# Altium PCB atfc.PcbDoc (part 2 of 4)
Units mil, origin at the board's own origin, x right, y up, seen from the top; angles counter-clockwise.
Board outline 6334.43 x 4147 mil, 6 copper layers (Component Side, Ground Plane (GND), GND/Signal, VCCO/Signal, VCCINT/VCCAUX, Bottom Side), stack 60.473 mil thick; 297 components, 274 nets, 1530 pads, 922 vias.
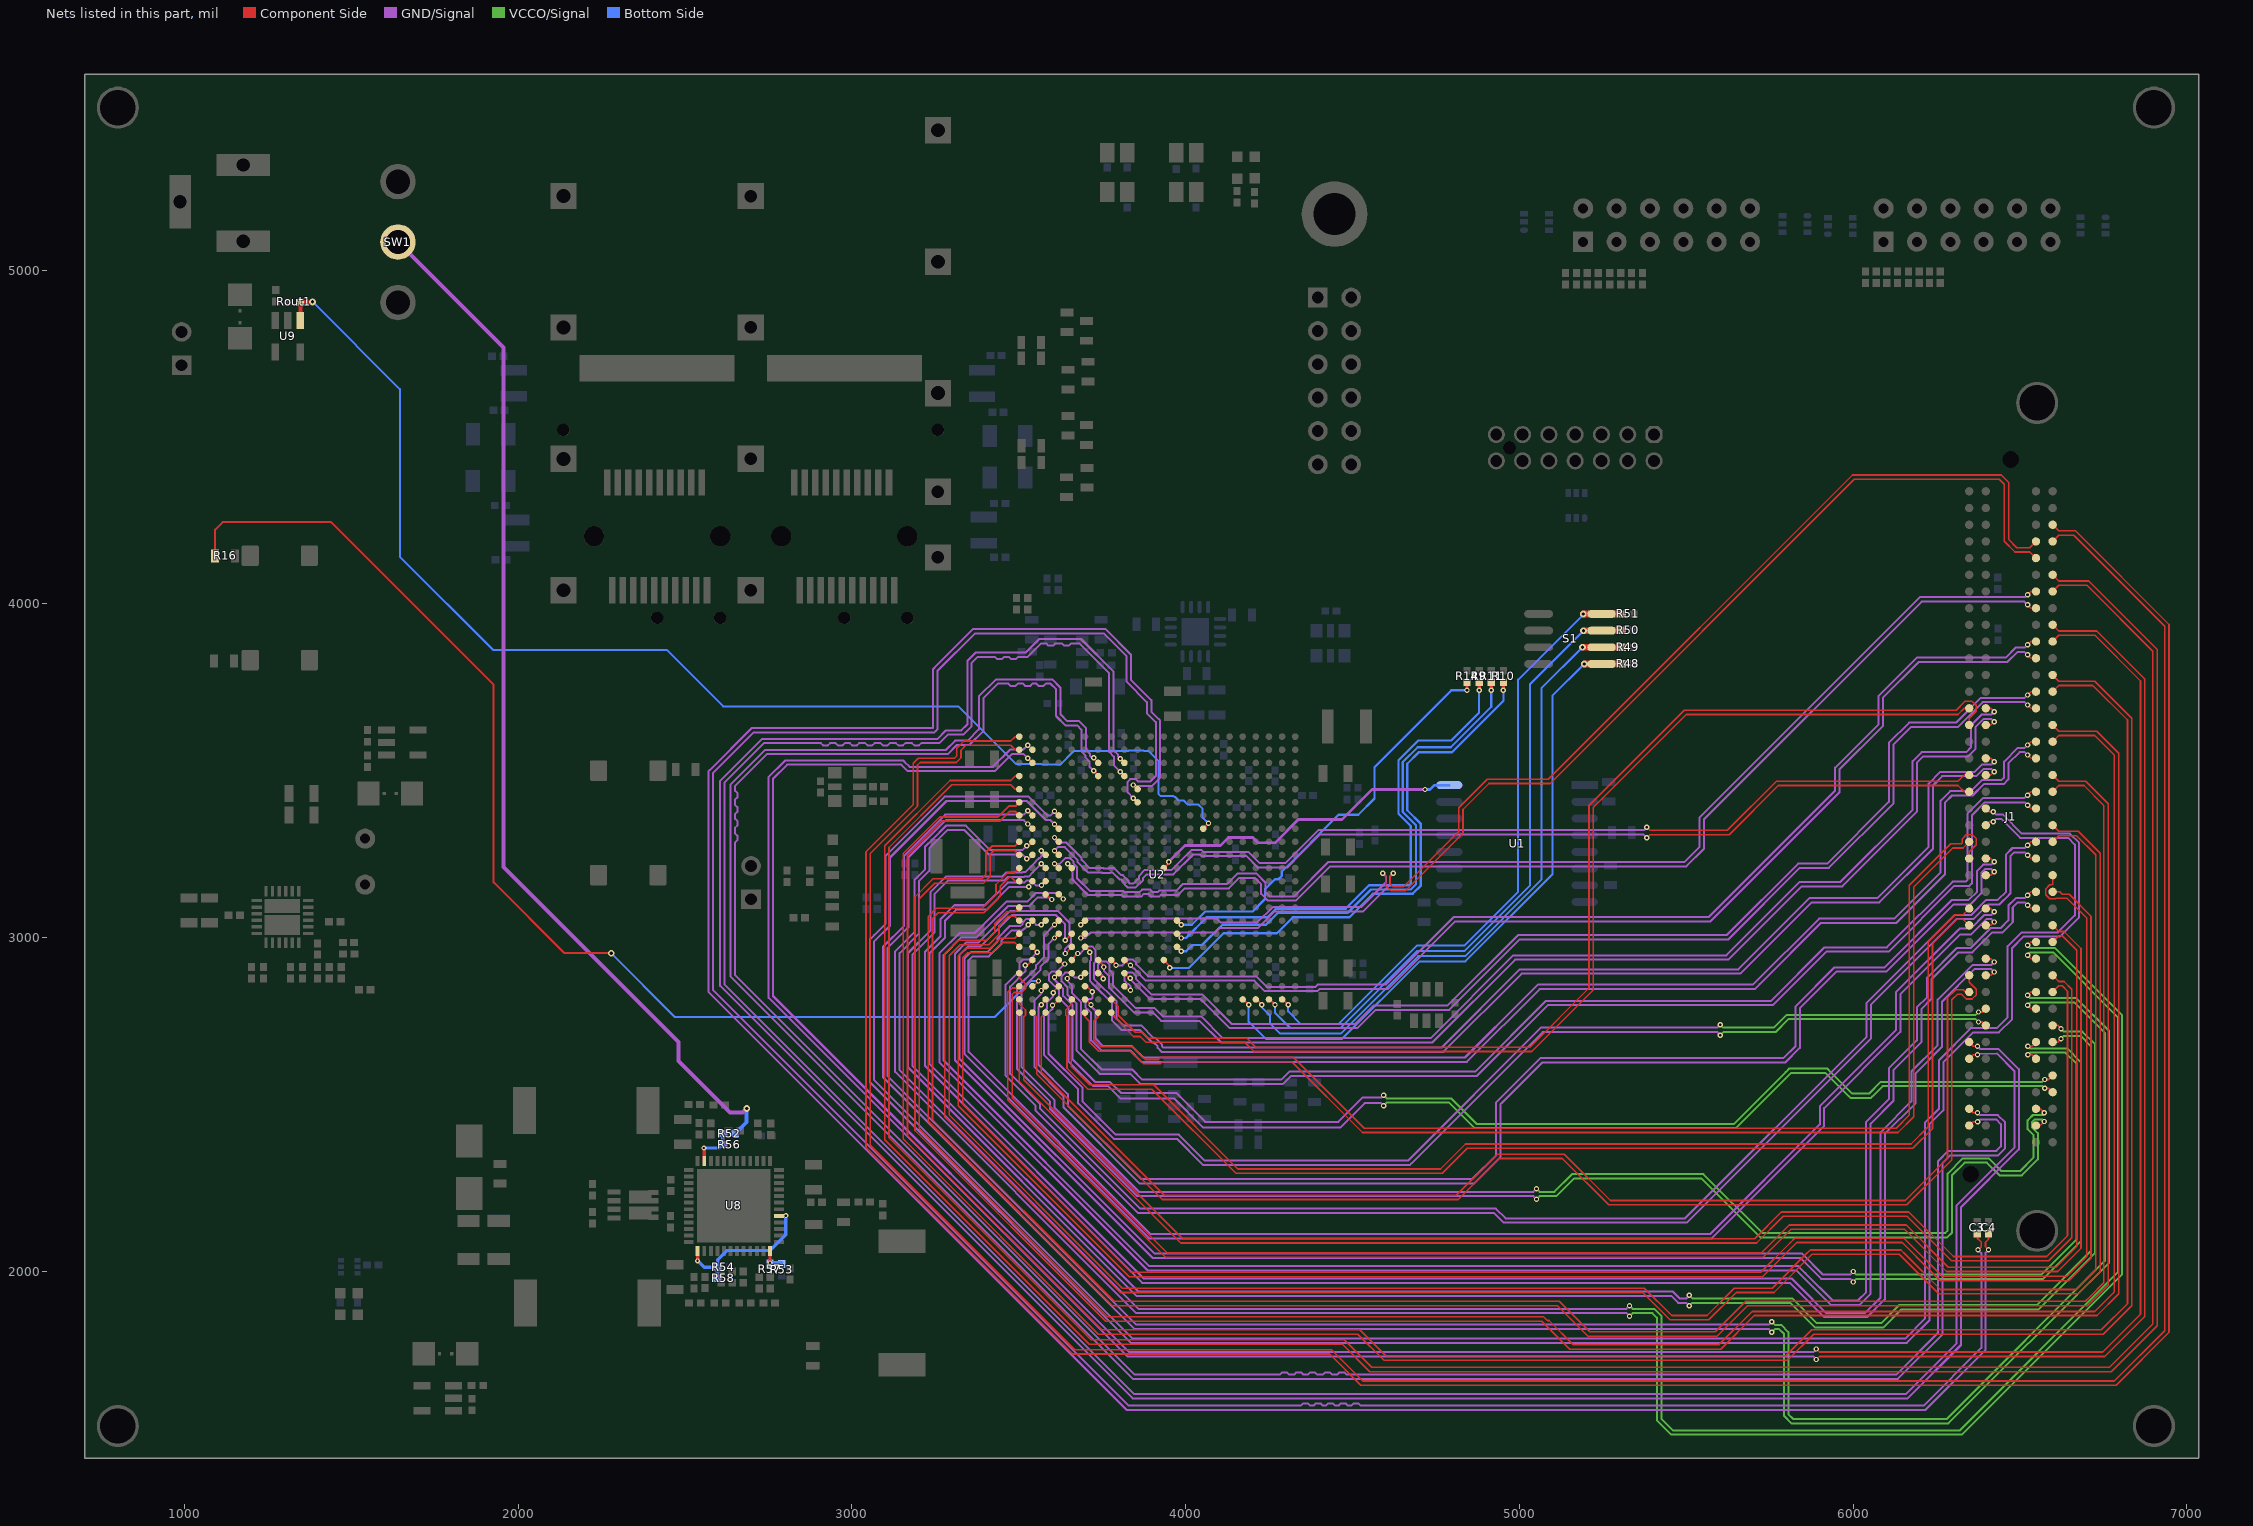
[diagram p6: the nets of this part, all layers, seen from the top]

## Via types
v1: diameter 16, hole 8, Component Side to Bottom Side, tented both sides, 374 vias
v2: diameter 20, hole 10, Component Side to Bottom Side, 243 vias
v3: diameter 16, hole 8, Component Side to Bottom Side, 222 vias
v4: diameter 15, hole 7, Component Side to Bottom Side, 58 vias
v5: diameter 25, hole 10, Component Side to Bottom Side, 20 vias
v6: diameter 19.68, hole 7.87, Component Side to Bottom Side, 4 vias
v7: diameter 20, hole 10, Component Side to Bottom Side, tented both sides, 1 vias

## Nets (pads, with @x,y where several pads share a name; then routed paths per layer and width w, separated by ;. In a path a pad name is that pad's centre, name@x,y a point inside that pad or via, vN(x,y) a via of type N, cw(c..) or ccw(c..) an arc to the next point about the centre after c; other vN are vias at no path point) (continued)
12V0_I_MON: Rout1.2 U2.H15 U9.1 | length 3847.6
  Component Side w6: U2.H15@4052.8,3326.8 v1(4068.54,3342.54)
  Component Side w12: Rout1.2@1346.84,4904.77 Rout1.2@1348.73,4904.77 ; U9.1@1348.73,4850.3 Rout1.2@1348.73,4904.77 ; v2(1384.15,4904.77) Rout1.2@1348.73,4904.77
  Bottom Side w6: v2(1384.15,4904.77) 1645.67,4643.25 1645.67,4141.33 1924.8,3862.2 2444.88,3862.2 2614.17,3692.91 3318.71,3692.91 3490.98,3520.65 3553.31,3520.65 3553.63,3520.96 3567.71,3520.96 3569.34,3519.33 3625.33,3519.33 3662.46,3556.46 3662.55,3556.46 3665.1,3559 3717.81,3559 3718.11,3558.7 3732.19,3558.7 3732.49,3559 3827.9,3559 3829.45,3560.54 3873.75,3560.54 3875.59,3558.7 3889.3,3558.7 3918,3530 3918,3431 3924,3425 3963,3425 3966,3422 3968.04,3422 3979.04,3411 3994.66,3411 4006.77,3398.89 4038.54,3398.89 4051.18,3386.25 4051.18,3359.91 v1(4068.54,3342.54)
BTN_RESETN: R16.1 U2.Y2 | length 3592
  Component Side w6: R16.1@1092.47,4144 1092.47,4222.47 1115,4245 1440,4245 1927,3758 1927,3166 2139,2954 v2@2279,2954 ; U2.Y2@3540.98,2846.98 U2.Y2@3540.98,2854.35 3543.33,2854.35 v1(3559.06,2870.08)
  Bottom Side w6: v2(2279,2953) 2470,2762 3427.35,2762 3504.18,2838.83 3504.43,2838.58 3535.93,2870.08 v1(3559.06,2870.08)
CCLK: U1.16 U2.L12 | length 979.7
  Component Side w6: U2.L12@3934.69,3208.68 3949,3223 v1(3949,3227) 3953,3227 v1@3954.37,3228.37
  GND/Signal w8: v1(3949,3227) 3998,3276 4104,3276 4128,3300 4201,3300 4217,3284 4267.31,3284 4337.31,3354 4363.04,3354 4363.37,3354.33 4468.5,3354.33 4558.17,3444 v3(4717,3444)
  Bottom Side w8: v3(4717,3444) 4732,3444 4745,3457 U1.16@4790,3457
DIP1: R48.1 S1.1 U2.AA18 | length 1992
  Component Side w6: U2.AA18@4170.91,2814.98 4173.2,2814.98 v1(4188.98,2799.21)
  Component Side w20: v2(5194,3820) S1.1@5246.49,3820 ; S1.1@5247.49,3821 R48.1@5306.27,3821
  Bottom Side w6: v1(4188.98,2799.21) 4188.98,2748.03 4240.16,2696.85 4468.5,2696.85 4700.79,2929.13 4838.31,2929.13 5098.43,3189.25 5098.43,3724.43 v2(5194,3820)
DIP2: R49.1 S1.2 U2.AA19 | length 1973
  Component Side w6: U2.AA19@4210.28,2814.98 4212.57,2814.98 v1(4228.35,2799.21)
  Component Side w20: v2(5189,3870) S1.2@5246.49,3870 R49.1@5307.27,3870
  Bottom Side w6: v1(4228.35,2799.21) 4228.35,2791.34 4251.97,2767.72 4251.97,2744.09 4283.46,2712.6 4464.57,2712.6 4696.85,2944.88 4837.09,2944.88 5066,3173.79 5066,3747 v2(5189,3870)
DIP3: R50.1 S1.3 U2.AA20 | length 1956.1
  Component Side w6: U2.AA20@4249.65,2814.98 4251.94,2814.98 v1(4267.72,2799.21)
  Component Side w20: v2(5192,3920) S1.3@5246.49,3920 ; S1.3@5248.49,3920 5247.49,3921 R50.1@5307.27,3921 R50.1@5309.27,3921
  Bottom Side w6: v1(4267.72,2799.21) 4267.72,2775.59 4314.15,2729.16 4462.66,2729.16 4694.14,2960.63 4835.87,2960.63 5032,3156.76 5032,3760 v2(5192,3920)
DIP4: R51.1 S1.4 U2.AA21 | length 1943.7
  Component Side w6: U2.AA21@4289.02,2814.98 4291.31,2814.98 v1(4307.09,2799.21)
  Component Side w20: v2(5191,3970) S1.4@5246.49,3970 R51.1@5307.27,3970 R51.1@5308.27,3970
  Bottom Side w6: v1(4307.09,2799.21) 4307.09,2779.53 4345.46,2741.16 4457.69,2741.16 4692.91,2976.38 4834.65,2976.38 4996.06,3137.8 4996.06,3773.19 5191,3968.13 v2(5191,3970)
EN: R52.2 SW1.2 | length 3164.7
  GND/Signal w12: SW1.2@1640,5084 1956,4768 1956,3212 2480.32,2687.68 2480.32,2630.68 2635,2476 2672.85,2476 v2(2685.03,2488.18)
  Bottom Side w12: R52.2@2650.48,2413 2685.03,2447.55 v2(2685.03,2488.18)
ES1: R52.1 R56.2 U8.23 | length 129
  Component Side w10: U8.23@2557.73,2331.43 v4@2557.73,2368.95
  Bottom Side w10: v4(2556.68,2370) 2603,2370 2613,2380 R52.1@2613,2411
ES2: R53.1 R57.2 U8.48 | length 70.4
  Component Side w10: v4@2754.58,2025.79 U8.48@2754.58,2061.14
  Bottom Side w10: v4(2754.69,2025.68) R53.1@2789.68,2025.68
ES3: R54.1 R58.2 U8.5 U8.37 | length 457.7
  Component Side w10: v4@2538.05,2032.36 U8.37@2538.05,2061.14 ; U8.5@2781.46,2166.76 2781.7,2167 v4(2802,2167)
  Bottom Side w10: v4@2538.68,2032 2557.68,2013 R54.1@2595,2013 ; R58.2@2596,1982 R54.1@2596,2012 ; R54.1@2597.95,2013 2597.95,2034.95 2625.61,2062.61 2754.61,2062.61 2802,2110 v4(2802,2167)
  other v4: 2537.68,2032
FMC_CLK0_M2C_N: J1.H5 U2.W4 | length 3490.6
  Component Side w5: v3(6573.44,2575.2) 6585.44,2575.2 J1.H5@6597.44,2587.2
  Component Side w6: v1(3607.04,2881.04) U2.W4@3619.72,2893.72
  GND/Signal w6: v1(3607.04,2881.04) 3607.04,2873.39 3633,2847.43 3633,2825.4 3661.3,2797.1 3661.3,2635.09 3728.38,2568 3773.22,2568 3806.22,2535 3971.99,2535 4058.53,2448.46 4457.46,2448.46 4529.47,2520.47 4585.48,2520.47 v3(4593,2527.99)
  VCCO/Signal w6: v3(4593,2527.99) 4602.25,2518.74 4794.92,2518.74 4871.4,2442.26 5643.05,2442.26 5797.79,2597 5808.79,2608 5922.2,2608 5933.2,2597 5997.38,2532.81 6047.37,2532.81 6082.68,2568.12 6566.35,2568.12 v3(6573.44,2575.2)
FMC_CLK0_M2C_P: J1.H4 U2.V4 | length 3589.2
  Component Side w5: v3(6573.44,2549.2) 6585.44,2549.2 J1.H4@6597.44,2537.2
  Component Side w6: U2.V4@3619.72,2933.09 3631.56,2921.26 v1(3637.8,2921.26)
  GND/Signal w6: v1(3637.8,2921.26) 3615.57,2899.04 3599.58,2899.04 3590,2889.46 3590,2872.04 3620,2842.04 3620,2820.01 3648.3,2791.71 3648.3,2629.7 3723,2555 3767.83,2555 3804.29,2518.54 3965.17,2518.54 4051.72,2432 4464.27,2432 4536.29,2504.02 4585.48,2504.02 v3(4593,2496.5)
  VCCO/Signal w6: v3(4593,2496.5) 4602.25,2505.74 4789.53,2505.74 4862.2,2433.07 4866.01,2429.26 5648.44,2429.26 5652.24,2433.07 5814.17,2595 5916.81,2595 5988.19,2523.62 5992,2519.81 6052.76,2519.81 6056.57,2523.62 6088.06,2555.12 6567.53,2555.12 v3(6573.44,2549.2)
FMC_CLK1_M2C_N: J1.G3 U2.T4 | length 4181.3
  Component Side w5: J1.G3@6547.44,2487.2 6560.44,2487.2 v3(6572.44,2475.2)
  Component Side w6: v1(3607.04,2999.15) U2.T4@3619.72,3011.83
  GND/Signal w6: v1(3607.04,2999.15) 3589.3,2981.41 3589.3,2936.84 3564.95,2912.49 3564.95,2902.86 3507.7,2845.62 3507.7,2613.3 3606.82,2514.18 3606.82,2492.18 3860.22,2238.78 5041.93,2238.78 v3(5051.18,2248.03)
  VCCO/Signal w6: v3(5051.18,2248.03) 5060.43,2238.78 5104.93,2238.78 5157.48,2291.34 5551.18,2291.34 5727.16,2115.36 6276.36,2115.36 6283,2122 6283,2293.38 6328.62,2339 6405.77,2339 6443.77,2301 6500,2301 6540,2341 6540,2409 6526,2423 6522.19,2426.81 6522.19,2452.28 6526,2456.09 6538.62,2468.7 6565.94,2468.7 v3(6572.44,2475.2)
FMC_CLK1_M2C_P: J1.G2 U2.R4 | length 4247.6
  Component Side w5: J1.G2@6547.44,2437.2 6560.44,2437.2 v3(6572.44,2449.2)
  Component Side w6: v1(3607.04,3038.52) U2.R4@3619.72,3051.2
  GND/Signal w6: v1(3607.04,3038.52) 3576.3,3007.78 3576.3,2942.22 3551.95,2917.87 3551.95,2908.25 3494.7,2851 3494.7,2607.91 3593.82,2508.8 3593.82,2486.8 3854.83,2225.78 5041.93,2225.78 v3(5051.18,2216.54)
  VCCO/Signal w6: v3(5051.18,2216.54) 5060.43,2225.78 5110.31,2225.78 5162.87,2278.34 5545.8,2278.34 5698.15,2125.98 5721.77,2102.36 6281.75,2102.36 6296,2116.62 6296,2288 6334,2326 6400.38,2326 6438.38,2288 6505.38,2288 6553,2335.62 6553,2414.38 6535.19,2432.19 6535.19,2446.9 6544,2455.7 6565.94,2455.7 v3(6572.44,2449.2)
FMC_LA00_CC_N: J1.G7 U2.U5 | length 5304.4
  Component Side w5: v3(6523.44,2675.2) 6535.44,2675.2 J1.G7@6547.44,2687.2
  Component Side w6: v1(3639.09,2952.46) U2.U5@3659.09,2972.46
  GND/Signal w6: v1(3639.09,2952.46) 3639.09,2966.38 3657.09,2984.38 3657.09,2999.29 3652.09,3004.29 3652.09,3045.29 3626.19,3071.19 3616.86,3080.52 3474.14,3080.52 3379.62,2986 3342.62,2986 3309,2952.38 3309,2632.62 3900.62,2041 5840.82,2041 5904.06,1977.75 5990.75,1977.75 v3(6000,1968.5)
  VCCO/Signal w6: v3(6000,1968.5) 6009.25,1977.75 6569.14,1977.75 6682.29,2090.91 6682.29,2627.43 6641.02,2668.7 6529.94,2668.7 v3(6523.44,2675.2)
FMC_LA00_CC_P: J1.G6 U2.T5 | length 5147.8
  Component Side w5: v3(6523.44,2649.2) 6535.44,2649.2 J1.G6@6547.44,2637.2
  Component Side w6: v1(3639.09,2991.83) U2.T5@3659.09,3011.83
  GND/Signal w6: v1(3639.09,2991.83) 3639.09,3039.91 3611.48,3067.52 3479.52,3067.52 3385,2973 3348,2973 3322,2947 3322,2638 3906,2054 5846.2,2054 5909.45,1990.75 5990.75,1990.75 v3(6000,2000)
  VCCO/Signal w6: v3(6000,2000) 6009.25,1990.75 6563.75,1990.75 6669.29,2096.29 6669.29,2622.05 6635.63,2655.7 6529.94,2655.7 v3(6523.44,2649.2)
FMC_LA01_CC_N: J1.D9 U2.AA4 | length 3324.7
  Component Side w5: v1(3601,2798) 3602.74,2798 U2.AA4@3619.72,2814.98 ; v3(6375.44,2777.2) 6387.44,2777.2
  GND/Signal w6: v1@3602.02,2798 v1(3601,2798) 3601,2787 3589,2775 3589,2653 3691.18,2550.82 3691.18,2508.82 3790,2410 3979.38,2410 4057.19,2332.19 4666.19,2332.19 5064.25,2730.25 5592.75,2730.25 v3(5602,2739.5)
  VCCO/Signal w6: v3(5602,2739.5) 5611.25,2730.25 5761.86,2730.25 5800.32,2768.7 6366.94,2768.7 v3(6375.44,2777.2)
FMC_LA01_CC_P: J1.D8 U2.Y4 | length 3389.2
  Component Side w5: v3(6375.44,2747.2) 6387.44,2747.2
  Component Side w6: v1(3603,2835) 3603,2837.63 U2.Y4@3619.72,2854.35
  GND/Signal w6: v1(3603,2835) 3603,2824.04 3584,2805.04 3584,2788.38 3575.81,2780.19 3576,2780 3576,2648 3575.81,2647.81 3678.18,2545.44 3678.18,2503.44 3784.62,2397 3974,2397 4048,2323 4051.81,2319.19 4671.58,2319.19 4675.38,2323 5069.63,2717.25 5592.75,2717.25 v3(5602,2708)
  VCCO/Signal w6: v3(5602,2708) 5611.25,2717.25 5767.25,2717.25 5805.7,2755.7 6366.94,2755.7 v3(6375.44,2747.2)
FMC_LA02_N: J1.H8 U2.K3 | length 5721.1
  Component Side w5: J1.H8@6597.44,2737.2 6612.44,2737.2 v3(6622.44,2727.2)
  Component Side w6: v1(3567.67,3260.74) U2.K3@3580.35,3248.06
  GND/Signal w6: v1(3567.67,3260.74) 3567.67,3243.67 3562.37,3238.37 3560.63,3238.37 3550.67,3228.41 3550.67,3227.46 3519.34,3196.13 3512.13,3196.13 3511,3195 3461.26,3195 3450.26,3184 3282.43,3184 3235.03,3136.61 3235.03,3021.13 3168.1,2954.2 3168.1,2611.51 3852.62,1927 5454.44,1927 5475.44,1906 5500,1906 v3(5509,1897)
  VCCO/Signal w6: v3(5509,1897) 5518.25,1906.25 5811.75,1906.25 5886,1832 6089.38,1832 6143.19,1885.81 6554.81,1885.81 6701,2032 6725,2056 6725,2680.38 6686.68,2718.7 6630.94,2718.7 v3(6622.44,2727.2)
FMC_LA02_P: J1.H7 U2.L3 | length 5613.8
  Component Side w5: J1.H7@6597.44,2687.2 6612.44,2687.2 v3(6622.44,2697.2)
  Component Side w6: v1(3567.67,3221.37) U2.L3@3580.35,3208.68
  GND/Signal w6: v1(3567.67,3221.37) 3552.28,3205.98 3552.01,3205.98 3542.06,3196.02 3542.06,3195.76 3529.43,3183.13 3517.51,3183.13 3516.38,3182 3466.64,3182 3455.64,3171 3287.81,3171 3248.03,3131.22 3248.03,3015.75 3181.1,2948.82 3181.1,2616.9 3858,1940 5459.83,1940 5480.83,1919 5499.5,1919 v3(5509,1928.5)
  VCCO/Signal w6: v3(5509,1928.5) 5518.25,1919.25 5817.14,1919.25 5891.38,1845 6084,1845 6134,1895 6137.81,1898.81 6549.42,1898.81 6712,2061.38 6712,2675 6681.3,2705.7 6630.94,2705.7 v3(6622.44,2697.2)
FMC_LA03_N: J1.G10 U2.G2 | length 6602.3
  Component Side w5: v3(6522.44,2827.2) 6532.44,2837.2 J1.G10@6547.44,2837.2
  Component Side w6: v1(3526.98,3380.17) U2.G2@3540.98,3366.17
  GND/Signal w6: v1(3526.98,3380.17) 3515.53,3368.71 3279.46,3368.71 3156.29,3245.54 3156.29,3036.29 3093.3,2973.3 3093.3,2581.32 3846.62,1828 3885,1828 3886,1827 5747,1827 v3(5756,1818)
  VCCO/Signal w6: v3(5756,1818) 5765.25,1827.25 5778.38,1827.25 5793,1812.63 5793,1567 5815,1545 6285.38,1545 6767,2026.62 6767,2720.38 6668.68,2818.7 6530.94,2818.7 v3(6522.44,2827.2)
FMC_LA03_P: J1.G9 U2.H2 | length 6514.1
  Component Side w5: v3(6522.44,2797.2) 6532.44,2787.2 J1.G9@6547.44,2787.2
  Component Side w6: v1(3526.98,3340.8) U2.H2@3540.98,3326.8
  GND/Signal w6: v1(3526.98,3340.8) 3515.53,3352.25 3281.39,3352.25 3169.29,3240.16 3169.29,3030.91 3106.3,2967.91 3106.3,2586.7 3852,1841 5747.5,1841 v3(5756,1849.5)
  VCCO/Signal w6: v3(5756,1849.5) 5765.25,1840.25 5783.77,1840.25 5806,1818.02 5806,1572.38 5820.38,1558 6280,1558 6754,2032 6754,2715 6663.3,2805.7 6530.94,2805.7 v3(6522.44,2797.2)
FMC_LA04_N: J1.H11 U2.AB1 | length 4496.4
  Component Side w5: U2.AB1@3501.61,2775.61 3501.61,2569.25 3985.44,2085.43 5710.11,2085.43 5790.04,2165.35 6161.42,2165.35 6291.34,2035.43 6295.15,2031.63 6585.44,2031.63 6655,2101.18 6655,2845.07 6631.37,2868.7 6615.94,2868.7 J1.H11@6597.44,2887.2
FMC_LA04_P: J1.H10 U2.AA1 | length 4480.9
  Component Side w5: U2.AA1@3501.61,2814.98 3501.61,2801.55 3519.96,2783.21 3519.96,2768.02 3514.61,2762.67 3514.61,2574.64 3990.83,2098.43 5704.72,2098.43 5784.65,2178.35 6166.8,2178.35 6300.53,2044.63 6580.06,2044.63 6642,2106.57 6642,2839.69 6625.98,2855.7 6615.94,2855.7 J1.H10@6597.44,2837.2
FMC_LA05_N: J1.D12 U2.M2 | length 5151.4
  Component Side w5: v1(3530,3153) 3530,3158.33 U2.M2@3540.98,3169.31 ; J1.D12@6397.44,2937.2 6412.44,2937.2 v3(6422.44,2927.2)
  GND/Signal w6: v1@3530,3152 3472,3152 3404.17,3084.17 3312.56,3084.17 3279,3050.62 3279,2999.62 3232,2952.62 3232,2622 3875,1979 5815.38,1979 5839.38,1955 5918.38,1876 6036,1876 6082,1922 6082,2417.38 6174,2509.38 6174,2599 6253,2678 6253,2814.09 6357.62,2918.7 6413.94,2918.7 v3(6422.44,2927.2) ; v1(3530,3153) v1@3530,3156
FMC_LA05_P: J1.D11 U2.M3 | length 5234.4
  Component Side w5: J1.D11@6397.44,2887.2 6412.44,2887.2 v3(6422.44,2897.2)
  Component Side w6: v1(3568,3157) U2.M3@3580.35,3169.31
  GND/Signal w6: v1(3568,3157) 3551,3157 3536.87,3171.13 3522.49,3171.13 3516.36,3165 3466.62,3165 3398.79,3097.17 3307.17,3097.17 3266,3056 3266,3005 3219,2958 3219,2616.62 3869.62,1966 5810,1966 5913,1863 6041.38,1863 6095,1916.62 6095,2412 6187,2504 6187,2593.62 6266,2672.62 6266,2808.7 6363,2905.7 6413.94,2905.7 v3(6422.44,2897.2)
FMC_LA06_N: J1.C11 U2.AB2 | length 3889.2
  Component Side w5: U2.AB2@3540.98,2775.61 3554.17,2762.43 3554.17,2591.5 3930.32,2215.35 4816.41,2215.35 4939.64,2338.58 5128.47,2338.58 5267.46,2199.6 6160.9,2199.6 6295.28,2333.98 6295.28,2813.7 6312.29,2830.71 6324.24,2830.71 6338.74,2816.2 6356.14,2816.2 6368.44,2828.51 6368.44,2845.9 6347.44,2866.9 J1.C11@6347.44,2887.2
FMC_LA06_P: J1.C10 U2.AB3 | length 3775.5
  Component Side w5: U2.AB3@3580.35,2775.61 3567.17,2762.43 3567.17,2596.88 3935.71,2228.35 4811.02,2228.35 4934.26,2351.58 5133.86,2351.58 5272.84,2212.6 6155.51,2212.6 6282.28,2339.36 6282.28,2819.08 6306.9,2843.71 6329.62,2843.71 6341.78,2831.55 J1.C10@6347.44,2837.2
FMC_LA07_N: J1.H14 U2.Y1 | length 4901.9
  Component Side w5: U2.Y1@3501.61,2854.35 3496.27,2849.01 3480.23,2849.01 3467.32,2836.09 3467.32,2514.3 3939.5,2042.12 5729.79,2042.12 5813.66,2125.98 6153.54,2125.98 6279.53,2000 6612.87,2000 6682.29,2069.42 6682.29,2967.78 6631.37,3018.7 6615.94,3018.7 J1.H14@6597.44,3037.2
FMC_LA07_P: J1.H13 U2.W1 | length 4890.9
  Component Side w5: U2.W1@3501.61,2893.72 3501.61,2880.29 3519.96,2861.95 3519.96,2846.76 3509.21,2836.01 3485.62,2836.01 3480.32,2830.71 3480.32,2519.68 3944.88,2055.12 5724.41,2055.12 5782.28,2112.98 5808.28,2138.98 6158.93,2138.98 6284.91,2013 6607.49,2013 6669.29,2074.8 6669.29,2962.4 6625.98,3005.7 6615.94,3005.7 J1.H13@6597.44,2987.2
FMC_LA08_N: J1.G13 U2.J2 | length 6789.6
  Component Side w5: v3(6522.44,2977.2) 6532.44,2987.2 J1.G13@6547.44,2987.2
  Component Side w6: v1(3523.62,3275.59) 3529.15,3275.59 U2.J2@3540.98,3287.43
  GND/Signal w6: v1(3523.62,3275.59) 3510.43,3262.4 3414.76,3262.4 3341.33,3335.83 3282.02,3335.83 3240.16,3293.98 3219.28,3273.1 3219.28,3205.32 3187.79,3173.83 3187.79,3017.2 3148.29,2977.7 3129.92,2959.33 3129.92,2597.69 3852.62,1875 5321,1875 v3(5330,1866)
  VCCO/Signal w6: v3(5330,1866) 5339.25,1875.25 5398.37,1875.25 5412,1861.62 5412,1553.62 5454.62,1511 6325.38,1511 6786.19,1971.81 6806,1991.62 6806,2767.38 6604.68,2968.7 6530.94,2968.7 v3(6522.44,2977.2)
FMC_LA08_P: J1.G12 U2.K2 | length 6703.7
  Component Side w5: v3(6522.44,2947.2) 6532.44,2937.2 J1.G12@6547.44,2937.2
  Component Side w6: v1(3523.61,3236.21) 3529.14,3236.21 U2.K2@3540.98,3248.06
  GND/Signal w6: v1(3523.61,3236.21) 3510.43,3249.4 3409.38,3249.4 3335.95,3322.83 3287.4,3322.83 3232.28,3267.72 3232.28,3199.94 3200.79,3168.44 3200.79,3011.81 3142.92,2953.95 3142.92,2603.08 3858,1888 5320.5,1888 v3(5330,1897.5)
  VCCO/Signal w6: v3(5330,1897.5) 5339.25,1888.25 5403.75,1888.25 5425,1867 5425,1559 5460,1524 6320,1524 6793,1997 6793,2762 6599.3,2955.7 6530.94,2955.7 v3(6522.44,2947.2)
FMC_LA09_N: J1.D15 U2.R2 | length 4345.2
  Component Side w5: J1.D15@6397.44,3087.2 6412.44,3087.2 v3(6422.44,3077.2)
  Component Side w6: v1(3528.3,3038.52) U2.R2@3540.98,3051.2
  GND/Signal w6: v1(3528.3,3038.52) 3515.84,3026.06 3515.13,3026.06 3511.18,3022.11 3479.11,3022.11 3449,2992 3449,2982.62 3410.38,2944 3362,2944 3350,2932 3350,2658 3896,2112 5571,2112 5900,2441 5900,2495 6128,2723 6128,2836 6315,3023 6319,3027 6351.62,3027 6393.32,3068.7 6413.94,3068.7 v3(6422.44,3077.2)
FMC_LA09_P: J1.D14 U2.R3 | length 4439.3
  Component Side w5: J1.D14@6397.44,3037.2 6412.44,3037.2 v3(6422.44,3047.2)
  Component Side w6: v1(3567.67,3038.52) U2.R3@3580.35,3051.2
  GND/Signal w6: v1(3567.67,3038.52) 3552.34,3038.52 3535.34,3055.52 3521.26,3055.52 3511.3,3045.56 3511.3,3040.61 3505.8,3035.11 3473.73,3035.11 3436,2997.38 3436,2988 3405,2957 3356.62,2957 3340.81,2941.19 3337,2937.38 3337,2652.62 3890.62,2099 5576.38,2099 5909.19,2431.81 5913,2435.62 5913,2489.62 6141,2717.62 6141,2830.62 6320.58,3010.19 6353.19,3010.19 6398.7,3055.7 6413.94,3055.7 v3(6422.44,3047.2)
FMC_LA10_N: J1.C15 U2.AB5 | length 3627.2
  Component Side w5: U2.AB5@3659.09,2775.61 3659.09,2763.27 3657.48,2761.66 3657.48,2614.17 3712.6,2559.06 3904.21,2559.06 4156.18,2307.09 4763.78,2307.09 4838.58,2381.89 6173.23,2381.89 6224.41,2433.07 6224.41,2987.48 6305.64,3068.7 6328.94,3068.7 J1.C15@6347.44,3087.2
FMC_LA10_P: J1.C14 U2.AA5 | length 3696.6
  Component Side w5: U2.AA5@3659.09,2814.98 3659.09,2801.55 3640.75,2783.21 3640.75,2768.02 3644.48,2764.29 3644.48,2608.79 3707.21,2546.06 3791.34,2546.06 3898.82,2546.06 4150.8,2294.09 4769.16,2294.09 4843.97,2368.89 6178.61,2368.89 6237.41,2427.69 6237.41,2982.09 6311.02,3055.7 6328.94,3055.7 J1.C14@6347.44,3037.2
FMC_LA11_N: J1.H17 U2.U1 | length 5562.1
  Component Side w5: U2.U1@3501.61,2972.46 3488.43,2985.65 3450.17,2985.65 3419.65,2955.13 3347.53,2955.13 3331.9,2939.5 3331.9,2501.45 3836.09,1997.25 5722.96,1997.25 5812.32,2086.61 5825.32,2099.61 6152.35,2099.61 6165.35,2086.61 6266.53,1985.44 6640.28,1985.44 6699.6,2044.75 6699.6,3059.06 6640.54,3118.11 6608.04,3118.11 6606.14,3116.2 6588.74,3116.2 6576.44,3128.51 6576.44,3145.9 6588.74,3158.2 6595.21,3158.2 6597.44,3160.43 J1.H17@6597.44,3187.2
FMC_LA11_P: J1.H16 U2.T1 | length 5552.8
  Component Side w5: U2.T1@3501.61,3011.83 3488.43,2998.65 3444.79,2998.65 3414.26,2968.13 3342.14,2968.13 3318.9,2944.88 3318.9,2496.06 3830.71,1984.25 5728.35,1984.25 5830.71,2086.61 6146.97,2086.61 6230.97,2002.62 6261.14,1972.44 6645.67,1972.44 6712.6,2039.37 6712.6,3064.44 6647.12,3129.92 6625.98,3129.92 6618.7,3137.2 J1.H16@6597.44,3137.2
FMC_LA12_N: J1.G16 U2.N3 | length 5300.2
  Component Side w5: v3(6522.44,3127.2) 6532.44,3137.2 J1.G16@6547.44,3137.2
  Component Side w6: U2.N3@3580.35,3129.94 3597.28,3113.02 3598.43,3111.87 3599.57,3113.02 v1@3600.72,3114.17 ; v1(3598.42,3114.17) v1@3600.72,3114.17 ; v1@3602.36,3115.81 v1@3600.72,3114.17
  GND/Signal w6: v1@3602.36,3115 3601.53,3114.17 v1(3598.42,3114.17) 3591.59,3121 3557,3121 3531,3095 3468,3095 3404.02,3031.02 3404.02,3030.88 3386.44,3013.31 3386.31,3013.31 3374,3001 3328,3001 3275,2948 3275,2632 3891,2016 5835.38,2016 5856.38,1995 5938.38,1913 6014,1913 6039,1938 6039,2448 6107,2516 6107,2608.38 6191,2692.38 6191,2791.38 6221.62,2822 6221.62,2880.62 6310,2969 6351.62,2969 6411.62,3029 6442,3029 6465,3052 6465,3096.38 6483.51,3114.9 6487.32,3118.7 6513.94,3118.7 v3(6522.44,3127.2)
FMC_LA12_P: J1.G15 U2.N4 | length 5365.4
  Component Side w5: v3(6522.44,3097.2) 6532.44,3087.2 J1.G15@6547.44,3087.2
  Component Side w6: U2.N4@3619.72,3129.94 v1(3633.72,3115.94)
  GND/Signal w6: v1(3633.72,3115.94) 3615.67,3134 3551.62,3134 3525.62,3108 3462.62,3108 3391.02,3036.4 3391.02,3036.27 3381.06,3026.31 3380.92,3026.31 3368.62,3014 3322.62,3014 3262,2953.38 3262,2626.62 3885.62,2003 5830,2003 5933,1900 6019.38,1900 6048.19,1928.81 6052,1932.62 6052,2442.62 6120,2510.62 6120,2603 6204,2687 6204,2786 6234.62,2816.62 6234.62,2875.23 6315.38,2956 6357,2956 6417,3016 6447.38,3016 6478,3046.62 6478,3091 6492.7,3105.7 6513.94,3105.7 v3(6522.44,3097.2)
FMC_LA13_N: J1.D18 U2.AA3 | length 3850.9
  Component Side w5: J1.D18@6397.44,3237.2 6412.44,3237.2 v3(6422.44,3227.2)
  Component Side w6: v1(3566.92,2799.21) 3566.92,2801.55 U2.AA3@3580.35,2814.98
  GND/Signal w6: v1(3566.92,2799.21) 3559.52,2791.8 3559.52,2618.59 3647,2531.11 3647,2497 3867,2277 4859,2277 4930.13,2348.13 4930.13,2506.33 4933.9,2510.1 5062.79,2639 5791,2639 5827.5,2675.5 5827.5,2794.5 5944,2911 6094,2911 6296,3113 6346,3113 6371,3138 6371,3200.09 6389.62,3218.7 6413.94,3218.7 v3(6422.44,3227.2)
FMC_LA13_P: J1.D17 U2.Y3 | length 3917.1
  Component Side w5: J1.D17@6397.44,3187.2 6412.44,3187.2 v3(6422.44,3197.2)
  Component Side w6: v1(3567.67,2841.67) U2.Y3@3580.35,2854.35
  GND/Signal w6: v1(3567.67,2841.67) 3567.67,2832.21 3546.52,2811.06 3546.52,2613.21 3634,2525.73 3634,2491.62 3861.62,2264 4864.38,2264 4870.38,2270 ; 4870.3,2270.09 4943,2342.79 4943,2500.82 4946.9,2504.72 5068.18,2626 5796.38,2626 5840.5,2670.12 5840.5,2789.12 5949.38,2898 6099.38,2898 6301.38,3100 6351.38,3100 6384,3132.62 6384,3194.7 6395,3205.7 6413.94,3205.7 v3(6422.44,3197.2)
FMC_LA14_N: J1.C19 U2.AB6 | length 3610.9
  Component Side w5: U2.AB6@3698.46,2775.61 3698.46,2763.27 3711.65,2750.09 3711.65,2688.48 3739.9,2660.23 3835.83,2660.23 3870.08,2625.98 3873.89,2622.18 3924.03,2622.18 3927.83,2625.98 3930.45,2628.6 4317.45,2628.6 4529.92,2416.13 6134.12,2416.13 6181.1,2463.12 6181.1,3152.04 6297.76,3268.7 6328.94,3268.7 J1.C19@6347.44,3287.2
FMC_LA14_P: J1.C18 U2.AB7 | length 3693.4
  Component Side w5: U2.AB7@3737.83,2775.61 3737.83,2763.27 3724.65,2750.09 3724.65,2693.86 3745.28,2673.23 3841.22,2673.23 3879.27,2635.18 3918.64,2635.18 3921.26,2637.8 3925.07,2641.6 4322.83,2641.6 4535.3,2429.13 6128.73,2429.13 6168.1,2468.5 6168.1,3157.43 6292.38,3281.7 6323.56,3281.7 6326.44,3284.59 6326.44,3295.9 6338.74,3308.2 6357.15,3308.2 6368.44,3296.91 6368.44,3278.51 6347.44,3257.51 J1.C18@6347.44,3237.2
FMC_LA15_N: J1.H20 U2.P1 | length 6086.7
  Component Side w5: U2.P1@3501.61,3090.57 3488.43,3077.39 3463.22,3077.39 3427.95,3042.12 3427.95,3015.75 3404.32,2992.13 3318.9,2992.13 3278.34,2951.57 3278.34,2463.12 3804.45,1937.01 5369,1937.01 5451.01,1855 5567.38,1855 5649.38,1937.01 5762.48,1937.01 5876.65,2051.18 6137.8,2051.18 6255.91,1933.07 6673.23,1933.07 6739.78,1999.62 6739.78,3253.42 6674.49,3318.7 6615.94,3318.7 J1.H20@6597.44,3337.2
FMC_LA15_P: J1.H19 U2.R1 | length 6000.5
  Component Side w5: U2.R1@3501.61,3051.2 3488.43,3064.39 3468.6,3064.39 3440.95,3036.73 3440.95,3010.36 3409.71,2979.13 3324.28,2979.13 3291.34,2946.18 3291.34,2468.5 3809.83,1950.01 5374.38,1950.01 5456.39,1868 5561.99,1868 5644,1950.01 5757.09,1950.01 5858.27,2051.18 5871.27,2064.18 6143.18,2064.18 6156.18,2051.18 6261.29,1946.07 6667.84,1946.07 6726.78,2005.01 6726.78,3248.03 6669.11,3305.7 6615.94,3305.7 J1.H19@6597.44,3287.2
FMC_LA16_N: J1.G19 U2.V2 | length 4230.2
  Component Side w5: v3(6522.44,3277.2) 6532.44,3287.2 J1.G19@6547.44,3287.2
  Component Side w6: v1(3519.68,2917.32) 3525.21,2917.32 U2.V2@3540.98,2933.09
  GND/Signal w6: v1@3523.61,2915.27 3521.57,2917.32 v1(3519.68,2917.32) 3519.68,2899.29 3474,2853.62 3474,2592 3563,2503 3563,2489 3864,2188 4929.38,2188 4958.38,2159 5496,2159 6040,2703 6040,2805 6303.7,3068.7 6354.32,3068.7 6398.62,3113 6433,3113 6458,3138 6458,3249.38 6477.32,3268.7 6513.94,3268.7 v3(6522.44,3277.2)
FMC_LA16_P: J1.G18 U2.U2 | length 4311.9
  Component Side w5: v3(6522.44,3247.2) 6532.44,3237.2 J1.G18@6547.44,3237.2
  Component Side w6: U2.U2@3540.98,2972.46 3540.98,2970.81 v1(3555.11,2956.69)
  GND/Signal w6: v1(3555.11,2956.69) 3532.74,2934.32 3512.64,2934.32 3502.68,2924.36 3502.68,2900.68 3461,2859 3461,2586.62 3550,2497.62 3550,2483.62 3858.62,2175 4924,2175 4953,2146 5501.38,2146 6053,2697.62 6053,2799.62 6309.09,3055.7 6359.7,3055.7 6404,3100 6438.38,3100 6467.19,3128.81 6471,3132.62 6471,3244 6482.7,3255.7 6513.94,3255.7 v3(6522.44,3247.2)
FMC_LA17_CC_N: J1.D21 U2.G4 | length 6897.2
  Component Side w5: J1.D21@6397.44,3387.2 6407.44,3377.2 v3(6419.44,3377.2)
  Component Side w6: v1(3607.04,3378.85) U2.G4@3619.72,3366.17
  GND/Signal w6: v1(3607.04,3378.85) 3593.85,3365.67 3586.54,3365.67 3529.76,3422.45 3278.08,3422.45 3101.17,3245.54 3101.17,3041.73 3066.93,3007.48 3053.93,2994.48 3053.93,2567.69 3835.62,1786 6161,1786 6228,1853 6228,2440.62 6270,2482.62 6270,2627.08 6359.46,2716.54 6436.38,2716.54 6476,2756.15 6476,2969 6510,3003 6618.38,3003 6677,3061.62 6677,3284.38 6649.38,3312 6505.6,3312 6448.89,3368.7 6427.94,3368.7 v3(6419.44,3377.2)
FMC_LA17_CC_P: J1.D20 U2.H4 | length 6811
  Component Side w5: J1.D20@6397.44,3337.2 6407.44,3347.2 v3(6419.44,3347.2)
  Component Side w6: v1(3607.04,3339.48) U2.H4@3619.72,3326.8
  GND/Signal w6: v1(3607.04,3339.48) 3593.85,3352.67 3581.16,3352.67 3524.37,3409.45 3283.46,3409.45 3114.17,3240.16 3114.17,3036.34 3066.93,2989.1 3066.93,2573.07 3841,1799 6155.62,1799 6215,1858.38 6215,2446 6257,2488 6257,2632.46 6354.07,2729.54 6431,2729.54 6463,2761.54 6463,2974.38 6504.62,3016 6613,3016 6664,3067 6664,3279 6644,3299 6500.21,3299 6443.51,3355.7 6427.94,3355.7 v3(6419.44,3347.2)
FMC_LA18_CC_N: J1.C23 U2.J4 | length 3019.6
  Component Side w5: v3(5381.89,3330.71) 5391.14,3321.46 5622.96,3321.46 5770.21,3468.7 6313.94,3468.7 6332.44,3487.2 J1.C23@6347.44,3487.2
  Component Side w6: v1(3607.04,3300.11) U2.J4@3619.72,3287.43
  GND/Signal w6: v1(3607.04,3300.11) 3607.04,3294.96 3616.8,3285.2 3641.98,3285.2 3688.41,3238.77 3688.41,3232.85 3712.6,3208.66 3753.19,3208.66 3754.42,3207.43 3768.5,3207.43 3769.73,3208.66 3786.1,3208.66 3807.29,3187.47 3811.63,3187.47 3829.2,3169.9 3829.2,3165.56 3832.03,3162.74 3844.26,3162.74 3859.51,3177.99 3859.51,3184.56 3877.95,3203 3958,3203 4003.06,3248.06 4017.28,3262.28 4047.86,3262.28 4053.05,3257.09 4187.79,3257.09 4221.69,3223.19 4298.99,3223.19 4362.67,3286.87 ; 4351.29,3275.68 4398.45,3322.83 5374.02,3322.83 v3(5381.89,3330.71)
FMC_LA18_CC_P: J1.C22 U2.K4 | length 2999.4
  Component Side w5: v3(5381.89,3299.21) 5391.14,3308.46 5628.35,3308.46 5775.59,3455.7 6313.94,3455.7 6332.44,3437.2 J1.C22@6347.44,3437.2
  Component Side w6: v1(3607.04,3260.74) U2.K4@3619.72,3248.06
  GND/Signal w6: v1(3607.04,3260.74) 3617.3,3271 3637.79,3271 3675.41,3233.38 3675.41,3227.47 3707.21,3195.66 3747.8,3195.66 3749.03,3194.43 3773.88,3194.43 3775.11,3195.66 3780.72,3195.66 3801.9,3174.47 3806.25,3174.47 3816.2,3164.52 3816.2,3160.17 3822.83,3153.54 3826.64,3149.74 3849.64,3149.74 3872.51,3172.61 3872.51,3179.17 3883.34,3190 3963.38,3190 4022.67,3249.28 4042.47,3249.28 4047.66,3244.09 4182.4,3244.09 4216.3,3210.19 4304.37,3210.19 4324,3229.82 4324,3230 4403.83,3309.83 5371.27,3309.83 v3(5381.89,3299.21)
FMC_LA19_N: J1.H23 U2.L1 | length 6472.7
  Component Side w5: U2.L1@3501.61,3208.68 3486.56,3193.63 3477.1,3193.63 3466.33,3193.63 3431.88,3159.19 3431.88,3129.92 3389.76,3087.8 3253.16,3087.8 3228.35,3062.99 3228.35,2450.12 3780.83,1897.64 5114,1897.64 5205.64,1806 5591.75,1806 5683.38,1897.64 6700.79,1897.64 6763.78,1960.63 6763.78,3401.57 6696.65,3468.7 6615.94,3468.7 J1.H23@6597.44,3487.2
FMC_LA19_P: J1.H22 U2.M1 | length 6385
  Component Side w5: U2.M1@3501.61,3169.31 3489.27,3169.31 3477.95,3180.63 3471.71,3180.63 3444.88,3153.8 3444.88,3124.54 3395.15,3074.8 3258.54,3074.8 3241.35,3057.61 3241.35,2455.5 3786.21,1910.64 5119.38,1910.64 5211.02,1819 5586.36,1819 5678,1910.64 6695.4,1910.64 6711.28,1926.52 6750.78,1966.01 6750.78,3396.19 6691.26,3455.7 6615.94,3455.7 J1.H22@6597.44,3437.2
FMC_LA20_N: J1.G22 U2.W5 | length 3625.5
  Component Side w5: U2.W5@3659.09,2891.38 U2.W5@3659.09,2893.72 ; v3(6522.44,3427.2) 6532.44,3437.2 J1.G22@6547.44,3437.2
  Component Side w6: v1(3645.67,2877.95) U2.W5@3659.09,2891.38
  GND/Signal w6: v1@3645.67,2881.47 v1(3645.67,2877.95) 3645.67,2870.72 3659,2857.38 3659,2834.75 3686.3,2807.45 3686.3,2666.7 3748,2605 3839.38,2605 3869.38,2575 4287,2575 4307,2595 4310.81,2598.81 4867.42,2598.81 5079.62,2811 5754,2811 5914,2971 6100.62,2971 6297.62,3168 6337.23,3168 6343,3173.77 6343,3372.38 6389.32,3418.7 6513.94,3418.7 v3(6522.44,3427.2)
FMC_LA20_P: J1.G21 U2.W6 | length 3719
  Component Side w5: v3(6522.44,3397.2) 6532.44,3387.2 J1.G21@6547.44,3387.2
  Component Side w6: v1(3685.78,2881.04) U2.W6@3698.46,2893.72
  GND/Signal w6: v1(3685.78,2881.04) 3666.62,2881.04 3652.71,2894.95 3638.63,2894.95 3628.67,2884.99 3628.67,2869.33 3646,2852 3646,2829.37 3673.3,2802.07 3673.3,2661.32 3742.62,2592 3834,2592 3864,2562 4292.38,2562 4316.19,2585.81 4872.81,2585.81 5085,2798 5759.38,2798 5919.38,2958 6106,2958 6303,3155 6348,3155 6356,3163 6356,3367 6394.7,3405.7 6513.94,3405.7 v3(6522.44,3397.2)
FMC_LA21_N: J1.H26 U2.J1 | length 6918.9
  Component Side w5: 3401.57,3255.91 3401.57,3188.98 3388.77,3176.17 3243.1,3176.17 3188.98,3122.05 3188.98,2422.56 3760.54,1851 5066.62,1851 5150.62,1767 5603,1767 5704,1868 6730.2,1868 6795.28,1933.07 6795.28,3552.63 6729.2,3618.7 6615.94,3618.7 J1.H26@6597.44,3637.2
  Component Side w6: 3401.57,3255.91 3419.91,3274.24 3488.43,3274.24 U2.J1@3501.61,3287.43
FMC_LA21_P: J1.H25 U2.K1 | length 6832.7
  Component Side w5: 3414.57,3250.52 3414.57,3183.59 3394.15,3163.17 3386.28,3163.17 3248.48,3163.17 3201.98,3116.66 3201.98,2427.94 3765.92,1864 5072,1864 5083,1853 5088.38,1853 5161.38,1780 5597.62,1780 5697.62,1880 6723.82,1880 6782.28,1938.46 6782.28,3547.24 6723.82,3605.7 6615.94,3605.7 J1.H25@6597.44,3587.2
  Component Side w6: 3414.57,3250.52 3425.29,3261.24 3488.43,3261.24 U2.K1@3501.61,3248.06
FMC_LA22_N: J1.G25 U2.AA6 | length 3517.7
  Component Side w5: U2.AA6@3698.46,2814.98 3700.75,2814.98 v1(3716.53,2799.21) ; v3(6522.44,3577.2) 6532.44,3587.2 J1.G25@6547.44,3587.2
  GND/Signal w6: v1(3716.53,2799.21) 3716.53,2793.86 3730,2780.38 3730,2698 3753,2675 3839,2675 3873,2641 4837,2641 5023,2827 5055,2859 5699.62,2859 5897.62,3057 6123,3057 6262.19,3196.19 6262.19,3410.58 6290.62,3439 6352,3439 6386,3473 6445,3473 6452,3480 6452,3527.38 6493.32,3568.7 6513.94,3568.7 v3(6522.44,3577.2)
FMC_LA22_P: J1.G24 U2.Y6 | length 3597
  Component Side w5: U2.Y6@3698.46,2854.35 3704.12,2854.35 v1(3720.22,2838.25) ; v3(6522.44,3547.2) 6532.44,3537.2 J1.G24@6547.44,3537.2
  GND/Signal w6: v1(3720.22,2838.25) 3720.22,2819.22 3717.21,2816.21 3709.49,2816.21 3699.53,2806.25 3699.53,2792.17 3709.49,2782.21 3709.79,2782.21 3717,2775 3717,2692.62 3743.81,2665.81 3747.62,2662 3833.62,2662 3867.62,2628 4842.38,2628 5060.38,2846 5705,2846 5720,2861 5903,3044 6128.38,3044 6275.19,3190.81 6275.19,3405.19 6296,3426 6357.38,3426 6391.38,3460 6450.38,3460 6465,3474.62 6465,3522 6498.7,3555.7 6513.94,3555.7 v3(6522.44,3547.2)
FMC_LA23_N: J1.D24 U2.V5 | length 3494.5
  Component Side w5: J1.D24@6397.44,3537.2 6412.44,3537.2 v3(6422.44,3527.2)
  Component Side w6: U2.V5@3659.09,2933.09 3659.09,2934.69 v1(3677.16,2952.75)
  GND/Signal w6: v1@3677.16,2949.46 v1(3677.16,2952.75) 3684.61,2952.75 3705.55,2973.69 3719.63,2973.69 3729.59,2963.73 3729.59,2927.6 3726,2924.01 3726,2876 3793,2809 3793,2757 3813,2737 3867.07,2737 3905.07,2699 3910.25,2699 3929,2680.25 3929,2675.07 3933.07,2671 4767,2671 5001,2905 5656,2905 5870,3119 6073,3119 6226,3272 6226,3461.38 6261.32,3496.7 6363.62,3496.7 6385.62,3518.7 6413.94,3518.7 v3(6422.44,3527.2)
FMC_LA23_P: J1.D23 U2.U6 | length 3438
  Component Side w5: J1.D23@6397.44,3487.2 6412.44,3487.2 v3(6422.44,3497.2)
  Component Side w6: U2.U6@3698.46,2972.46 3700.81,2972.46 3712.65,2960.63 3712.59,2960.58 v1(3712.59,2956.69)
  GND/Signal w6: v1(3712.59,2956.69) 3716.59,2952.69 3716.59,2932.99 3713,2929.4 3713,2870.62 3724,2859.62 3780,2803.62 3780,2751.62 3807.62,2724 3861.69,2724 3899.69,2686 3904.87,2686 3916,2674.87 3916,2669.69 3927.69,2658 4772.38,2658 5006.38,2892 5661.38,2892 5875.38,3106 6078.38,3106 6239,3266.62 6239,3456 6266.7,3483.7 6369,3483.7 6391,3505.7 6413.94,3505.7 v3(6422.44,3497.2)
FMC_LA24_N: J1.H29 U2.F1 | length 7341.1
  Component Side w5: 3263.78,3362.2 3153.54,3251.97 3153.54,2396.79 3738.34,1812 4516,1812 4594,1734 5803.38,1734 5881.38,1812 6749.01,1812 6834.65,1897.64 6834.65,3657.48 6723.42,3768.7 6615.94,3768.7 J1.H29@6597.44,3787.2
  Component Side w6: 3263.78,3362.2 3438.06,3362.2 3470.07,3394.22 3490.3,3394.22 U2.F1@3501.61,3405.54
FMC_LA24_P: J1.H28 U2.G1 | length 7250.3
  Component Side w5: 3269.16,3349.2 3166.54,3246.58 3166.54,2407.46 3749,1825 4521.38,1825 4599.38,1747 5798,1747 5876,1825 6743.62,1825 6821.65,1903.02 6821.65,3652.1 6718.04,3755.7 6615.94,3755.7 J1.H28@6597.44,3737.2
  Component Side w6: 3269.16,3349.2 3443.44,3349.2 3471.72,3377.48 3490.3,3377.48 U2.G1@3501.61,3366.17
FMC_LA25_N: J1.G28 U2.Y9 | length 3394.5
  Component Side w5: v3(6522.44,3727.2) 6532.44,3737.2 J1.G28@6547.44,3737.2
  Component Side w6: U2.Y9@3816.57,2854.35 3828.41,2842.52 v1(3834.65,2842.52)
  GND/Signal w6: v1(3834.65,2842.52) 3834.65,2855.35 3829,2861 3826.96,2861 3817,2870.96 3817,2888.29 3823.67,2894.95 3826.91,2894.95 3826.96,2895 3841.04,2895 3851,2885.04 3851,2876.34 3897.34,2830 4049.38,2830 4137.38,2742 4508.81,2742 4563.81,2797 4785,2797 4996,3008 5621,3008 5835,3222 5922,3222 6107,3407 6107,3583.38 6167.62,3644 6307.91,3644 6382.62,3718.7 6513.94,3718.7 v3(6522.44,3727.2)
FMC_LA25_P: J1.G27 U2.W9 | length 3323.9
  Component Side w5: U2.W9@3816.57,2893.72 3816.57,2892.09 3830.66,2878 3832.3,2878 v1(3834,2878) ; v3(6522.44,3697.2) 6532.44,3687.2 J1.G27@6547.44,3687.2
  Component Side w6: v1@3830.71,2879.59 v1@3832.3,2878
  GND/Signal w6: v1(3834,2878) 3831.05,2878 3831,2877.95 3832.48,2876.48 3891.95,2817 4044,2817 4119,2742 4132,2729 4514.19,2729 4569.19,2784 4790.38,2784 5001.38,2995 5626.38,2995 5840.38,3209 5927.38,3209 6120,3401.62 6120,3578 6173,3631 6313.3,3631 6388,3705.7 6513.94,3705.7 v3(6522.44,3697.2)
FMC_LA26_N: J1.D27 U2.W7 | length 3444.2
  Component Side w5: J1.D27@6397.44,3687.2 6412.44,3687.2 v3(6422.44,3677.2)
  Component Side w6: U2.W7@3737.83,2893.72 3753,2878.56 v1(3753,2877)
  GND/Signal w6: v1(3753,2877) 3753,2884.16 3742,2895.16 3742,2900.96 3738,2904.96 3738,2919.04 3747.96,2929 3762.23,2929 3772,2919.23 3772,2901.93 3783,2890.93 3783,2856.43 3850.21,2789.21 3906.79,2789.21 3932,2764 4046.38,2764 4111.38,2699 4734,2699 4982,2947 5620,2947 5840,3167 5962,3167 6178,3383 6178,3529 6205,3556 6339,3556 6353,3570 6353,3636.38 6385.32,3668.7 6413.94,3668.7 v3(6422.44,3677.2)
FMC_LA26_P: J1.D26 U2.V7 | length 3374.9
  Component Side w5: J1.D26@6397.44,3637.2 6412.44,3637.2 v3(6422.44,3647.2)
  Component Side w6: U2.V7@3737.83,2933.09 3755,2915.93 v1(3755,2912)
  GND/Signal w6: v1(3755,2912) 3755,2900.55 3770,2885.55 3770,2851.04 3844.83,2776.21 3901.4,2776.21 3926.62,2751 4041,2751 4106,2686 4739.38,2686 4987.38,2934 5625.38,2934 5845.38,3154 5967.38,3154 6191,3377.62 6191,3523.62 6210.38,3543 6344.38,3543 6366,3564.62 6366,3631 6390.7,3655.7 6413.94,3655.7 v3(6422.44,3647.2)
FMC_LA27_N: J1.C27 U2.AB8 | length 3367.9
  Component Side w5: U2.AB8@3777.2,2775.61 3785.23,2767.59 3785.23,2762.63 3843.92,2703.94 3864.29,2703.94 3881.23,2687 4177,2687 4205,2659 5036.95,2659 5221.66,2843.71 5221.66,3390.95 5499.41,3668.7 6313.94,3668.7 6332.44,3687.2 J1.C27@6347.44,3687.2
FMC_LA27_P: J1.C26 U2.AA8 | length 3487.9
  Component Side w5: U2.AA8@3777.2,2814.98 3798.23,2793.96 3798.23,2768.02 3849.31,2716.94 3869.67,2716.94 3887.92,2698.7 4183.69,2698.7 4210.38,2672 5031.57,2672 5208.66,2849.09 5208.66,3396.34 5212.47,3400.15 5494.03,3681.7 6308.56,3681.7 6335.06,3708.2 6356.14,3708.2 6368.44,3695.9 6368.44,3678.51 6347.44,3657.51 J1.C26@6347.44,3637.2
FMC_LA28_N: J1.H32 U2.B2 | length 8391.6
  Component Side w5: v3(5889.76,1736.22) 5899.01,1745.47 6753.34,1745.47 6870.08,1862.2 6873.89,1866.01 6873.89,3774.42 6870.08,3778.23 6729.6,3918.7 6615.94,3918.7 J1.H32@6597.44,3937.2
  Component Side w6: v1(3526.98,3577.02) U2.B2@3540.98,3563.02
  GND/Signal w6: v1(3526.98,3577.02) 3513.8,3563.83 3474.58,3563.83 3422.56,3511.81 3173.23,3511.81 3157.48,3527.56 3153.67,3531.37 2800.38,3531.37 2796.58,3527.56 2750.78,3481.76 2750.78,2819.84 3825.15,1745.47 5880.52,1745.47 v3(5889.76,1736.22)
FMC_LA28_P: J1.H31 U2.C2 | length 8305.4
  Component Side w5: v3(5889.76,1767.72) 5899.01,1758.47 6747.96,1758.47 6860.89,1871.4 6860.89,3769.03 6724.22,3905.7 6615.94,3905.7 J1.H31@6597.44,3887.2
  Component Side w6: v1(3526.98,3537.65) U2.C2@3540.98,3523.65
  GND/Signal w6: v1(3526.98,3537.65) 3513.8,3550.83 3479.96,3550.83 3427.94,3498.81 3167.84,3498.81 3148.29,3518.37 2805.77,3518.37 2763.78,3476.38 2763.78,2825.22 3830.53,1758.47 5880.52,1758.47 v3(5889.76,1767.72)
FMC_LA29_N: J1.G31 U2.V8 | length 3345.1
  Component Side w5: v3(6522.44,3877.2) 6532.44,3887.2 J1.G31@6547.44,3887.2
  Component Side w6: U2.V8@3777.2,2933.09 3792.16,2918.14 3792.98,2917.32 v1@3795.28,2919.62 ; v1(3791.33,2917.32) v1@3792.97,2917.32
  GND/Signal w6: v1(3791.33,2917.32) 3810.6,2917.32 3827.6,2934.32 3841.68,2934.32 3851.64,2924.36 3851.64,2919.76 3887.4,2884 4211.19,2884 4242.38,2852.81 4389.42,2852.81 4391.81,2855.19 4395.62,2859 4599.62,2859 4802.62,3062 5567,3062 5946,3441 5946,3509.38 6076,3639.38 6076,3724.38 6190.62,3839 6456.62,3839 6486.32,3868.7 6513.94,3868.7 v3(6522.44,3877.2)
FMC_LA29_P: J1.G30 U2.V9 | length 3290.4
  Component Side w5: U2.V9@3816.57,2933.09 v1@3828.41,2921.26 ; v3(6522.44,3847.2) 6532.44,3837.2 J1.G30@6547.44,3837.2
  Component Side w6: v1@3828.41,2921.26 3832.35,2917.32 v1(3834.64,2917.32)
  GND/Signal w6: v1@3832.63,2917.32 v1(3834.64,2917.32) 3844.95,2907 3846.01,2907 3863,2890.01 3863,2888.95 3880.95,2871 4205.81,2871 4237,2839.81 4394.81,2839.81 4401,2846 4605,2846 4808,3049 5572.38,3049 5959,3435.62 5959,3504 6089,3634 6089,3719 6196,3826 6462,3826 6491.7,3855.7 6513.94,3855.7 v3(6522.44,3847.2)
FMC_LA30_N: J1.H35 U2.D1 | length 7959.5
  Component Side w5: U2.D1@3501.61,3484.28 3489.27,3484.28 3476.09,3471.09 3293.83,3471.09 3098.43,3275.69 3098.43,2395 3711.15,1782.28 4469.72,1782.28 4552,1700 6773.5,1700 6779.5,1706 6910.64,1837.13 6910.64,3863.65 6705.59,4068.7 6615.94,4068.7 J1.H35@6597.44,4087.2
FMC_LA30_P: J1.H34 U2.E1 | length 7873.3
  Component Side w5: U2.E1@3501.61,3444.91 3489.27,3444.91 3476.09,3458.09 3299.21,3458.09 3111.43,3270.3 3111.43,2400.39 3716.54,1795.28 4475.11,1795.28 4557.38,1713 6768.12,1713 6897.64,1842.52 6897.64,3858.27 6700.2,4055.7 6615.94,4055.7 J1.H34@6597.44,4037.2
FMC_LA31_N: J1.G34 U2.L4 | length 3534.8
  Component Side w5: v3(6522.44,4027.2) 6532.44,4037.2 J1.G34@6547.44,4037.2
  Component Side w6: v1(3607.04,3221.37) U2.L4@3619.72,3208.68
  GND/Signal w6: v1(3607.04,3221.37) 3622.37,3221.37 3639.37,3238.37 3653.45,3238.37 3663.41,3228.41 3663.41,3222.5 3674.42,3211.49 3674.42,3178.61 3712.79,3140.24 3813.38,3140.24 3817.33,3136.29 3861.58,3136.29 3869.46,3144.17 3894.31,3144.17 3902.18,3136.29 3915.6,3136.29 3920.31,3141 3972,3141 3992,3161 4124,3161 4155,3192 4212.38,3192 4239,3165.38 4239,3137 4252,3124 4325,3124 4428,3227 5495,3227 5540,3272 5540,3360.38 6199.62,4020 6515.24,4020 v3(6522.44,4027.2)
FMC_LA31_P: J1.G33 U2.L5 | length 3484.5
  Component Side w5: v3(6522.44,3997.2) 6532.44,3987.2 J1.G33@6547.44,3987.2
  Component Side w6: v1(3646.41,3221.37) U2.L5@3659.09,3208.68
  GND/Signal w6: v1(3646.41,3221.37) 3646.41,3221.11 3661.42,3206.1 3661.42,3173.23 3707.41,3127.24 3808,3127.24 3811.94,3123.29 3866.97,3123.29 3874.84,3131.17 3888.92,3131.17 3896.8,3123.29 3920.99,3123.29 3925.69,3128 3977.38,3128 3997.38,3148 4129.38,3148 4160.38,3179 4207,3179 4226,3160 4226,3131.62 4242.81,3114.81 4246.62,3111 4330.38,3111 4334.19,3114.81 4433.38,3214 5500.38,3214 5553,3266.62 5553,3355 6205,4007 6512.65,4007 v3(6522.44,3997.2)
FMC_LA32_N: J1.H38 U2.A1 | length 8431.5
  Component Side w5: U2.A1@3501.61,3602.39 3489.27,3602.39 3476.09,3589.2 3335.82,3589.2 3314,3567.38 3314,3544.38 3307.62,3538 3199.32,3538 3183.85,3522.53 3183.85,3399.09 3042.12,3257.35 3042.12,2372.57 3662.09,1752.59 4431.41,1752.59 4525,1659 6787.62,1659 6946.07,1817.45 6946.07,3938.46 6665.82,4218.7 6615.94,4218.7 J1.H38@6597.44,4237.2
FMC_LA32_P: J1.H37 U2.B1 | length 8345.4
  Component Side w5: U2.B1@3501.61,3563.02 3489.27,3563.02 3476.09,3576.2 3341.2,3576.2 3327,3562 3327,3539 3313,3525 3204.7,3525 3196.85,3517.15 3196.85,3393.7 3055.12,3251.97 3055.12,2377.95 3667.48,1765.59 4436.79,1765.59 4530.38,1672 6782.24,1672 6933.07,1822.83 6933.07,3933.07 6660.44,4205.7 6615.94,4205.7 J1.H37@6597.44,4187.2
FMC_LA33_N: J1.G37 U2.T6 | length 3771.6
  Component Side w5: v3(4622.05,3192.91) 4612.8,3183.67 4612.8,3161.42 4620.67,3153.54 4653.54,3153.54 4818,3318 4818,3389.38 4903.62,3475 5086.62,3475 5997.63,4386.01 6443.4,4386.01 6447.2,4382.2 6465.76,4363.65 6465.76,4192.91 6489.96,4168.7 6528.94,4168.7 J1.G37@6547.44,4187.2
  Component Side w6: v1(3685.78,2999.15) U2.T6@3698.46,3011.83
  GND/Signal w6: v1(3685.78,2999.15) 3699.52,2999.15 3716.52,3016.15 4089.24,3016.15 4102.36,3029.27 4216.95,3029.27 4266.42,3078.74 4531.57,3078.74 4612.8,3159.97 4612.8,3183.67 v3(4622.05,3192.91)
FMC_LA33_P: J1.G36 U2.R6 | length 3770.8
  Component Side w5: v3(4590.55,3192.91) 4599.8,3183.67 4599.8,3156.03 4615.29,3140.54 4658.93,3140.54 4690.29,3171.91 4831,3312.62 4831,3384 4909,3462 5092,3462 6003.01,4373.01 6438.01,4373.01 6452.76,4358.27 6452.76,4187.53 6484.58,4155.7 6528.94,4155.7 J1.G36@6547.44,4137.2
  Component Side w6: v1(3685.78,3038.52) U2.R6@3698.46,3051.2
  GND/Signal w6: v1(3685.78,3038.52) 3705.06,3057.8 3845.62,3057.8 3845.82,3058 4091.61,3058 4103.88,3045.73 4215.02,3045.73 4261.03,3091.74 4526.19,3091.74 4599.8,3165.35 4599.8,3183.67 v3(4590.55,3192.91)
FMC_MGT_C2M_N: J1.C3 U2.C7 | length 7170.7
  Component Side w5: J1.C3@6347.44,2487.2 6359.44,2475.2 v3(6372.44,2475.2)
  Component Side w6: v1(3724.41,3539.37) 3724.41,3537.07 U2.C7@3737.83,3523.65
  GND/Signal w6: v1@3728.19,3539.37 v1(3724.41,3539.37) 3718.75,3539.37 3712.72,3545.41 3712.72,3551.82 3700.79,3563.75 3700.79,3628.62 3684.39,3645.02 3680.58,3648.83 3645.15,3648.83 3625,3668.98 3625,3749.38 3600.38,3774 3432,3774 3380.7,3722.7 3380.7,3624.14 3347.11,3590.55 3309.55,3590.55 3281.99,3562.99 2740.16,3562.99 2636.61,3459.44 2636.61,2883.01 3841.62,1678 6134,1678 6267,1811 6267,2324.62 6290.38,2348 6434,2348 6455.5,2369.5 6455.5,2446.57 6433.47,2468.61 6379.04,2468.61 v3(6372.44,2475.2)
FMC_MGT_C2M_P: J1.C2 U2.D7 | length 7170.1
  Component Side w5: J1.C2@6347.44,2437.2 6359.24,2449.01 v3(6372.64,2449.01)
  Component Side w6: v1(3724.41,3500) 3737.83,3486.57 U2.D7@3737.83,3484.28
  GND/Signal w6: v1(3724.41,3500) 3712,3512.41 3712,3527.74 3699.72,3540.02 3699.72,3546.44 3687.79,3558.36 3687.79,3623.24 3675.2,3635.83 3639.76,3635.83 3612.98,3662.61 3612,3663.59 3612,3744 3595,3761 3581,3761 3574,3754 3560,3754 3553,3761 3541,3761 3534,3754 3520,3754 3513,3761 3497,3761 3490,3754 3476,3754 3469,3761 3437.38,3761 3393.7,3717.32 3393.7,3618.76 3352.49,3577.55 3314.94,3577.55 3287.38,3549.99 2745.54,3549.99 2649.61,3454.06 2649.61,3441 2656.61,3434 2656.61,3420 2649.61,3413 2649.61,3398 2656.61,3391 2656.61,3377 2649.61,3370 2649.61,3357 2656.61,3350 2656.61,3336 2649.61,3329 2649.61,3313 2656.61,3306 2656.61,3292 2649.61,3285 2649.61,2888.39 3847,1691 4282,1691 4289,1698 4303,1698 4310,1691 4325,1691 4332,1698 4346,1698 4353,1691 4366,1691 4373,1698 4387,1698 4394,1691 4411,1691 4418,1698 4432,1698 4439,1691 4454,1691 4461,1698 4475,1698 4482,1691 6128.62,1691 6254,1816.38 6254,2330 6285,2361 6428.62,2361 6442.5,2374.89 6442.5,2441.18 6428.08,2455.61 6379.24,2455.61 v3(6372.64,2449.01)
FMC_MGT_CLK_N: C4.2 U2.E10 | length 7537.3
  Component Side w5: v3(6405.51,2064.96) 6396.26,2074.21 6396.26,2087.21 6405.51,2096.46 C4.2@6405.51,2114.17
  Component Side w6: v1(3843.26,3457.59) U2.E10@3855.94,3444.91
  GND/Signal w6: v1@3839.45,3453.78 v1(3843.26,3457.59) 3845.85,3455 3899.38,3455 3919.69,3475.31 3923.5,3479.12 3923.5,3650.88 3919.69,3654.69 3897,3677.38 3897,3711.38 3836,3772.38 3836,3848.38 3759.38,3925 3363.62,3925 3246.81,3808.19 3243,3804.38 3243,3629.38 3241.81,3628.19 2700.19,3628.19 2574,3502 2570.19,3498.19 2570.19,2838.42 3823.62,1585 6216.38,1585 6397,1765.62 6397,2056.45 v3(6405.51,2064.96)
FMC_MGT_CLK_P: C3.2 U2.F10 | length 7533.2
  Component Side w5: C3.2@6371.51,2114.17 6371.51,2099.86 6383.26,2088.11 6383.26,2074.21 v3(6374.02,2064.96)
  Component Side w6: v1(3843.26,3418.22) U2.F10@3855.94,3405.54
  GND/Signal w6: v1(3843.26,3418.22) 3826,3435.48 3826,3467 3834,3475 3851,3475 3858,3468 3894,3468 3910.5,3484.5 3910.5,3645.5 3884,3672 3884,3706 3823,3767 3823,3843 3754,3912 3369,3912 3256,3799 3256,3624 3251,3619 3247.19,3615.19 2705.58,3615.19 2583.19,3492.81 2583.19,2843.81 3829,1598 4345,1598 4352,1605 4366,1605 4373,1598 4383,1598 4390,1605 4404,1605 4411,1598 4420,1598 4427,1605 4441,1605 4448,1598 4458,1598 4465,1605 4479,1605 4486,1598 4496,1598 4503,1605 4517,1605 4524,1598 6211,1598 6384,1771 6384,2054.98 v3(6374.02,2064.96)
FMC_MGT_M2C_N: J1.C7 U2.C9 | length 7784.8
  Component Side w5: J1.C7@6347.44,2687.2 6359.44,2675.2 v3(6372.44,2675.2)
  Component Side w6: v1(3803.89,3536.33) U2.C9@3816.57,3523.65
  GND/Signal w6: v1(3803.89,3536.33) 3797.71,3542.51 3797.71,3547.85 3783.46,3562.1 3783.46,3797.91 3686.49,3894.89 3561.54,3894.89 3520.99,3854.33 3371.38,3854.33 3346,3828.95 3346,3638.72 3328.28,3621 3282,3621 3257,3596 2731.16,3596 2605.11,3469.95 2605.11,2855.51 3840.95,1619.67 6163.05,1619.67 6323,1779.62 6323,2192.62 6496.06,2365.68 6496.06,2606.01 6434.87,2667.2 6380.44,2667.2 v3(6372.44,2675.2)
FMC_MGT_M2C_P: J1.C6 U2.D9 | length 7782.9
  Component Side w5: J1.C6@6347.44,2637.2 6359.44,2649.2 v3(6372.44,2649.2)
  Component Side w6: v1(3803.89,3496.96) U2.D9@3816.57,3484.28
  GND/Signal w6: 3629,3882 3629.11,3881.89 ; 3657,3882 3656.89,3881.89 ; v1(3803.89,3496.96) 3784.71,3516.14 3784.71,3542.47 3770.46,3556.71 3770.46,3792.53 3681.1,3881.89 3656.89,3881.89 ; v3(6372.44,2649.2) 6375.13,2651.9 6431.29,2652.4 6483.06,2600.62 6483.06,2371.06 6310,2198 6310,1785 6157.67,1632.67 3846.33,1632.67 2618.11,2860.89 2618.11,3464.57 2736.54,3583 2907,3583 2914,3576 2928,3576 2935,3583 2951,3583 2958,3576 2972,3576 2979,3583 2994,3583 3001,3576 3015,3576 3022,3583 3040,3583 3047,3576 3061,3576 3068,3583 3086,3583 3093,3576 3107,3576 3114,3583 3132,3583 3139,3576 3153,3576 3160,3583 3180,3583 3187,3576 3201,3576 3208,3583 3262.38,3583 3287.38,3608 3333.67,3608 3359,3633.33 3359,3823.57 3376.76,3841.33 3428,3841.33 3435,3834.33 3449,3834.33 3456,3841.33 3470,3841.33 3477,3834.33 3491,3834.33 3498,3841.33 3526.37,3841.33 3566.93,3881.89 3582,3881.89 3589,3874.89 3603,3874.89 3610,3881.89 3629.11,3881.89 ; 3629.11,3881.89 3636,3875 3650,3875 3656.89,3881.89
FPGA_TCK: R10.1 U2.V12 | length 1688.8
  Component Side w6: U2.V12@3934.69,2933.09 3952.75,2915.03 v1(3952.75,2909.44)
  Component Side w10: v3(4952,3741) R10.1@4952,3765.27
  Bottom Side w6.89: v1(3952.75,2909.44) 4009.44,2909.44 4113.51,3013.51 4273.35,3013.51 4320.68,3060.83 4489.97,3060.83 4560.83,3131.7 4679.97,3131.7 4704.72,3156.46 4704.72,3340.74 4663.57,3381.89 4663.57,3520.82 4697.88,3555.12 4796.95,3555.12 4952,3710.17 v3(4952,3741)
FPGA_TDI: R14.1 U2.R13 | length 1268.8
  Component Side w6: U2.R13@3974.06,3051.2 v1(3986.74,3038.52)
  Component Side w10: v3(4843,3741) R14.1@4843,3765.27
  Bottom Side w6.89: v1(3986.74,3038.52) 4018.48,3038.52 4058.7,3078.74 4200.74,3078.74 4238,3116 4238,3145 4268.46,3175.46 4278.13,3175.46 4287.73,3185.06 4287.73,3197.73 4458,3368 4517,3368 4566,3417 4566,3510.88 4796.12,3741 v3(4843,3741)
FPGA_TDO: R11.1 U2.U13 | length 1593.7
  Component Side w6: U2.U13@3974.06,2972.46 v1(3986.74,2959.78)
  Component Side w10: v3(4915.67,3741) R11.1@4915.67,3765.27
  Bottom Side w6.89: v1(3986.74,2959.78) 4002.04,2959.78 4020.33,2978.07 4049.31,2978.07 4110.24,3039 4240.97,3039 4275.69,3073.72 4484.63,3073.72 4555.5,3144.59 4674.63,3144.59 4690.24,3160.2 4690.24,3336.99 4650.69,3376.55 4650.69,3526.16 4695.39,3570.87 4794.47,3570.87 4915.67,3692.07 v3(4915.67,3741)
FPGA_TMS: R9.1 U2.T13 | length 1549.4
  Component Side w6: U2.T13@3974.06,3011.83 v1(3986.74,2999.15)
  Component Side w10: v3(4879.33,3741) R9.1@4879.33,3765.27
  Bottom Side w6.89: v1(3986.74,2999.15) 4001.15,2999.15 4063.5,3061.5 4063.56,3061.44 4245.18,3061.44 4270.35,3086.61 4479.29,3086.61 4550.16,3157.48 4669.29,3157.48 4674.68,3162.87 4674.68,3334.32 4637.8,3371.21 4637.8,3531.5 4696.85,3590.55 4795.92,3590.55 4879,3673.63 v3@4879,3741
